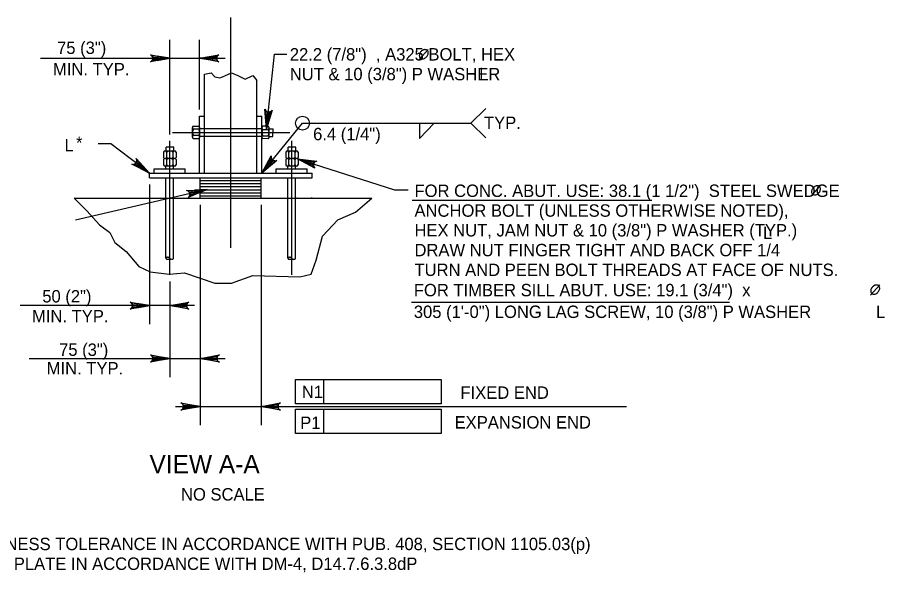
# Model space of a CAD drawing. Extents: x -13 to 81, y -176 to 0.
# Drawn here: x 13.47 to 21.86, y -148.39 to -143.01 of the extents above; entities that cross this region are included whole.
import ezdxf

# ---------------------------------------------------------------- set-up
doc = ezdxf.new("R2010")
doc.units = 0
for name, color, linetype in [('Level 3', 7, 'Continuous'), ('Level 4', 7, 'Continuous'), ('Level 52', 7, 'Continuous')]:
    doc.layers.add(name, color=color, linetype=linetype)

msp = doc.modelspace()

# ---------------------------------------------------------------- linework, layer by layer
at = {"layer": 'Level 3'}
for p, q in [((15.5355, -145.2405), (15.5355, -143.0105)), ((15.2822, -144.5168), (15.2822, -143.5601)), ((15.7888, -144.5168), (15.7888, -143.6213)), ((15.235, -143.9656), (15.2822, -143.9656)), ((15.235, -144.5168), (15.235, -143.9656)), ((15.7888, -143.9656), (15.836, -143.9656)), ((15.836, -144.5168), (15.836, -143.9656)), ((15.1642, -144.1685), (15.1645, -144.0775)), ((15.2265, -144.0938), (15.175, -144.0936)), ((15.1752, -144.0626), (15.2266, -144.0627)), ((15.2368, -144.1687), (15.2371, -144.0778)), ((15.2371, -144.0861), (15.836, -144.0861)), ((15.8358, -144.1703), (15.836, -144.0793)), ((15.8466, -144.0954), (15.898, -144.0955)), ((15.8981, -144.0645), (15.8467, -144.0644)), ((15.9085, -144.1705), (15.9087, -144.0795)), ((15.9087, -144.0887), (15.9448, -144.0888)), ((15.9447, -144.1625), (15.9448, -144.0888)), ((14.9705, -144.1231), (16.1081, -144.1231)), ((15.1747, -144.1825), (15.2262, -144.1827)), ((15.2263, -144.1538), (15.1748, -144.1536)), ((15.2369, -144.1608), (15.8358, -144.1608)), ((15.8464, -144.1554), (15.8979, -144.1555)), ((15.8978, -144.1844), (15.8464, -144.1843)), ((15.9085, -144.1624), (15.9447, -144.1625)), ((14.9107, -144.3038), (14.9108, -144.2676)), ((14.9846, -144.2678), (14.9108, -144.2676)), ((14.945, -145.5032), (14.945, -144.2057)), ((14.9845, -144.304), (14.9846, -144.2678)), ((16.1657, -144.2678), (16.0918, -144.2676)), ((16.0918, -144.3038), (16.0918, -144.2676)), ((16.1261, -145.5032), (16.1261, -144.2057)), ((16.1656, -144.304), (16.1657, -144.2678)), ((14.8865, -144.3144), (14.8864, -144.3658)), ((14.9926, -144.304), (14.9016, -144.3038)), ((14.9175, -144.3658), (14.9176, -144.3144)), ((14.9774, -144.366), (14.9776, -144.3146)), ((15.0065, -144.3146), (15.0064, -144.3661)), ((16.0677, -144.3144), (16.0675, -144.3658)), ((16.1737, -144.304), (16.0827, -144.3038)), ((16.0986, -144.3658), (16.0987, -144.3144)), ((16.1586, -144.366), (16.1587, -144.3146)), ((16.1876, -144.3146), (16.1875, -144.3661)), ((14.8864, -144.387), (14.8862, -144.4384)), ((14.9923, -144.4493), (14.9012, -144.4491)), ((14.9924, -144.3767), (14.9014, -144.3764)), ((14.908, -144.4774), (14.908, -144.4491)), ((14.9173, -144.4385), (14.9174, -144.3871)), ((14.9773, -144.4387), (14.9774, -144.3872)), ((14.9827, -144.4774), (14.9827, -144.4493)), ((15.0063, -144.3872), (15.0062, -144.4387)), ((16.0675, -144.387), (16.0674, -144.4384)), ((16.1733, -144.4493), (16.0823, -144.4491)), ((16.1735, -144.3767), (16.0825, -144.3764)), ((16.0891, -144.4774), (16.0891, -144.4491)), ((16.0984, -144.4385), (16.0985, -144.3871)), ((16.1584, -144.4387), (16.1585, -144.3872)), ((16.1638, -144.4774), (16.1638, -144.4493)), ((16.1874, -144.3872), (16.1873, -144.4387)), ((14.7481, -144.564), (14.7481, -144.5168)), ((14.7481, -144.5168), (16.3229, -144.5168)), ((14.7953, -144.5168), (14.7953, -144.4774)), ((14.7953, -144.4774), (15.0946, -144.4774)), ((15.0946, -144.5168), (15.0946, -144.4774)), ((15.9764, -144.4774), (16.2757, -144.4774)), ((15.9764, -144.5168), (15.9764, -144.4774)), ((16.2757, -144.5168), (16.2757, -144.4774)), ((16.3229, -144.564), (16.3229, -144.5168)), ((14.7481, -144.564), (16.3229, -144.564)), ((14.908, -144.7608), (14.908, -144.564)), ((14.9827, -144.7608), (14.9827, -144.564)), ((15.2402, -144.7608), (15.2402, -144.564)), ((15.2402, -144.5893), (15.5355, -144.5893)), ((15.2402, -144.6188), (15.5355, -144.6188)), ((15.5355, -144.5893), (15.8308, -144.5893)), ((15.5355, -144.6188), (15.8308, -144.6188)), ((15.8308, -144.7608), (15.8308, -144.564)), ((16.0891, -144.7608), (16.0891, -144.564)), ((16.1638, -144.7608), (16.1638, -144.564)), ((15.2402, -144.6483), (15.5355, -144.6483)), ((15.2402, -144.6779), (15.5355, -144.6779)), ((15.2402, -144.7074), (15.5355, -144.7074)), ((15.5355, -144.6483), (15.8308, -144.6483)), ((15.5355, -144.6779), (15.8308, -144.6779)), ((15.5355, -144.7074), (15.8308, -144.7074)), ((14.0217, -144.7608), (16.9022, -144.7608)), ((14.908, -145.3418), (14.908, -144.7608)), ((14.9827, -145.3421), (14.9827, -144.7608)), ((15.2402, -144.7369), (15.5355, -144.7369)), ((15.5355, -144.7369), (15.8308, -144.7369)), ((16.0891, -145.3418), (16.0891, -144.7608)), ((16.1638, -145.3421), (16.1638, -144.7608))]:
    msp.add_line(p, q, dxfattribs=at)
for points in [[(15.2822, -143.5601), (15.3455, -143.5478), (15.3823, -143.5846), (15.4313, -143.5968), (15.4558, -143.5846), (15.5417, -143.5478), (15.6029, -143.5723), (15.6765, -143.6091), (15.75, -143.5723), (15.7888, -143.6213)], [(14.7481, -144.5167), (14.5782, -144.4323), (14.5957, -144.4331), (14.6091, -144.4275), (14.6183, -144.4188), (14.6242, -144.4076), (14.6258, -144.3932), (14.6202, -144.3765), (14.7481, -144.5167), (14.6258, -144.3932), (14.6242, -144.4076), (14.7481, -144.5167), (14.6183, -144.4188), (14.6091, -144.4275), (14.7481, -144.5167), (14.5957, -144.4331)], [(15.2973, -144.6779), (15.1237, -144.7542), (15.1354, -144.7413), (15.1398, -144.7274), (15.1391, -144.7148), (15.1342, -144.7031), (15.1241, -144.6926), (15.1078, -144.6862), (15.2973, -144.6779), (15.1241, -144.6926), (15.1342, -144.7031), (15.2973, -144.6779), (15.1391, -144.7148), (15.1398, -144.7274), (15.2973, -144.6779), (15.1354, -144.7413)], [(14.0217, -144.7608), (14.1442, -144.8834), (14.2668, -145.0182), (14.3649, -145.0917), (14.4139, -145.1897), (14.5243, -145.2755), (14.6468, -145.4225), (14.7572, -145.4715), (14.941, -145.496), (15.0881, -145.4837), (15.3823, -145.5817), (15.5417, -145.5817), (15.75, -145.5083), (16.2036, -145.5205), (16.3139, -145.496), (16.3629, -145.3612), (16.4242, -145.1284), (16.5712, -144.9692), (16.7429, -144.8957), (16.9022, -144.7608)]]:
    msp.add_lwpolyline(points, dxfattribs=at)
for centre, radius, start, end in [((15.212, -144.1236), 0.0477, 140.8735, 218.7735), ((15.1811, -144.078), 0.0167, 111.11045, 181.65056), ((15.1811, -144.078), 0.0167, 181.65056, 248.53656), ((15.1893, -144.1235), 0.0477, 320.8735, 38.7735), ((15.2205, -144.0781), 0.0167, 291.11045, 357.99644), ((15.2205, -144.0781), 0.0167, 357.99644, 68.53656), ((15.8836, -144.1254), 0.0477, 140.93154, 218.83154), ((15.8527, -144.0798), 0.0167, 111.16848, 181.7086), ((15.8527, -144.0798), 0.0167, 181.7086, 248.59459), ((15.8609, -144.1253), 0.0477, 320.93154, 38.83154), ((15.892, -144.0799), 0.0167, 291.16848, 358.05448), ((15.892, -144.0799), 0.0167, 358.05448, 68.59459), ((15.1794, -144.1679), 0.0152, 107.27531, 252.37169), ((15.2217, -144.1681), 0.0152, 287.27531, 72.37169), ((15.851, -144.1698), 0.0152, 107.33335, 252.42973), ((15.8933, -144.1699), 0.0152, 287.33335, 72.42973), ((14.902, -144.3597), 0.0167, 201.16848, 271.7086), ((14.902, -144.3204), 0.0167, 88.05448, 158.59459), ((14.902, -144.3204), 0.0167, 21.16848, 88.05447), ((14.9475, -144.3287), 0.0477, 230.93154, 308.83154), ((14.9475, -144.3515), 0.0477, 50.93154, 128.83154), ((14.9919, -144.3614), 0.0152, 197.33335, 342.42973), ((14.992, -144.319), 0.0152, 17.33335, 162.42973), ((16.0831, -144.3597), 0.0167, 201.16848, 271.7086), ((16.0831, -144.3204), 0.0167, 88.05448, 158.59459), ((16.0831, -144.3597), 0.0167, 271.7086, 338.59459), ((16.0831, -144.3204), 0.0167, 21.16848, 88.05447), ((16.1286, -144.3287), 0.0477, 230.93154, 308.83154), ((16.1286, -144.3515), 0.0477, 50.93154, 128.83154), ((16.173, -144.3614), 0.0152, 197.33335, 342.42973), ((16.1731, -144.319), 0.0152, 17.33335, 162.42973), ((14.9018, -144.4323), 0.0167, 201.16848, 271.7086), ((14.9019, -144.393), 0.0167, 88.05448, 158.59459), ((14.9018, -144.4323), 0.0167, 271.7086, 338.59459), ((14.9019, -144.393), 0.0167, 21.16848, 88.05447), ((14.9474, -144.4014), 0.0477, 230.93154, 308.83154), ((14.9473, -144.4241), 0.0477, 50.93154, 128.83154), ((14.9918, -144.434), 0.0152, 197.33335, 342.42973), ((14.9919, -144.3917), 0.0152, 17.33335, 162.42973), ((16.0829, -144.4323), 0.0167, 201.16848, 271.7086), ((16.083, -144.393), 0.0167, 88.05448, 158.59459), ((16.0829, -144.4323), 0.0167, 271.7086, 338.59459), ((16.083, -144.393), 0.0167, 21.16848, 88.05447), ((16.1285, -144.4014), 0.0477, 230.93154, 308.83154), ((16.1284, -144.4241), 0.0477, 50.93154, 128.83154), ((16.1729, -144.434), 0.0152, 197.33335, 342.42973), ((16.173, -144.3917), 0.0152, 17.33335, 162.42973), ((14.9135, -145.3418), 0.00549, 142.06928, 180.00001), ((14.9135, -145.3418), 0.00549, 180.00001, 217.93074), ((14.9197, -145.3466), 0.0133, 117.99032, 142.06928), ((14.9197, -145.3369), 0.0133, 217.93074, 242.0097), ((14.9238, -145.3543), 0.0221, 102.4157, 117.99032), ((14.9238, -145.3292), 0.0221, 242.0097, 257.58432), ((14.9265, -145.3666), 0.0347, 90.00001, 102.4157), ((14.9265, -145.3169), 0.0347, 257.58432, 270.00001), ((14.9265, -145.3666), 0.0347, 77.58432, 90.00001), ((14.9265, -145.3169), 0.0347, 270.00001, 282.4157), ((14.9292, -145.3543), 0.0221, 62.0097, 77.58432), ((14.9292, -145.3292), 0.0221, 282.4157, 297.99032), ((14.9333, -145.3466), 0.0133, 37.93074, 62.0097), ((14.9333, -145.3369), 0.0133, 297.99032, 322.06928), ((14.9395, -145.3418), 0.00549, 0.00001, 37.93074), ((14.9395, -145.3418), 0.00549, 322.06928, 0.00001), ((14.9505, -145.3421), 0.00549, 179.99999, 217.93072), ((14.9566, -145.3373), 0.0133, 217.93072, 242.00968), ((14.9607, -145.3296), 0.0221, 242.00968, 257.5843), ((14.9634, -145.3173), 0.0347, 257.5843, 269.99999), ((14.9634, -145.3173), 0.0347, 269.99999, 282.41568), ((14.9662, -145.3296), 0.0221, 282.41568, 297.9903), ((14.9703, -145.3373), 0.0133, 297.9903, 322.06926), ((14.9764, -145.3421), 0.00549, 322.06926, 359.99999), ((14.9764, -145.3421), 0.00549, 359.99999, 1.75704), ((16.0946, -145.3418), 0.00549, 142.06928, 180.00001), ((16.0946, -145.3418), 0.00549, 180.00001, 217.93074), ((16.1008, -145.3466), 0.0133, 117.99032, 142.06928), ((16.1008, -145.3369), 0.0133, 217.93074, 242.0097), ((16.1049, -145.3543), 0.0221, 102.4157, 117.99032), ((16.1049, -145.3292), 0.0221, 242.0097, 257.58432), ((16.1076, -145.3666), 0.0347, 90.00001, 102.4157), ((16.1076, -145.3169), 0.0347, 257.58432, 270.00001), ((16.1076, -145.3666), 0.0347, 77.58432, 90.00001), ((16.1076, -145.3169), 0.0347, 270.00001, 282.4157), ((16.1103, -145.3543), 0.0221, 62.0097, 77.58432), ((16.1103, -145.3292), 0.0221, 282.4157, 297.99032), ((16.1144, -145.3466), 0.0133, 37.93074, 62.0097), ((16.1144, -145.3369), 0.0133, 297.99032, 322.06928), ((16.1206, -145.3418), 0.00549, 0.00001, 37.93074), ((16.1206, -145.3418), 0.00549, 322.06928, 0.00001), ((16.1316, -145.3421), 0.00549, 179.99999, 217.93072), ((16.1377, -145.3373), 0.0133, 217.93072, 242.00968), ((16.1418, -145.3296), 0.0221, 242.00968, 257.5843), ((16.1445, -145.3173), 0.0347, 257.5843, 269.99999), ((16.1445, -145.3173), 0.0347, 269.99999, 282.41568), ((16.1473, -145.3296), 0.0221, 282.41568, 297.9903), ((16.1514, -145.3373), 0.0133, 297.9903, 322.06926), ((16.1575, -145.3421), 0.00549, 322.06926, 359.99999), ((16.1575, -145.3421), 0.00549, 359.99999, 1.75704)]:
    msp.add_arc(centre, radius, start, end, dxfattribs=at)
at = {"layer": 'Level 4'}
for p, q in [((14.945, -144.1432), (14.945, -143.2267)), ((15.235, -143.9031), (15.235, -143.2267)), ((17.3581, -143.4196), (17.4477, -143.3215)), ((13.696, -143.4067), (15.4802, -143.4067)), ((15.8818, -144.0886), (15.9601, -143.3666)), ((15.9601, -143.3666), (16.0801, -143.3666)), ((17.8608, -144.0344), (18.0057, -143.8913)), ((15.836, -144.5168), (16.2301, -144.0344)), ((16.2301, -144.0344), (17.8608, -144.0344)), ((17.3622, -144.0344), (17.3622, -144.1812)), ((17.3622, -144.1812), (17.5036, -144.0344)), ((17.8608, -144.0344), (18.0057, -144.1775)), ((14.3738, -144.2345), (14.2538, -144.2345)), ((14.7481, -144.5167), (14.3738, -144.2345)), ((15.2973, -144.6779), (14.034, -144.9719)), ((14.7481, -144.6265), (14.7481, -145.9802)), ((21.1541, -144.737), (21.2437, -144.6389)), ((16.1746, -144.7608), (16.1795, -144.7559)), ((16.1795, -144.7559), (16.1844, -144.7608)), ((16.316, -144.7608), (16.3229, -144.7539)), ((17.292, -144.7788), (19.6116, -144.7788)), ((15.2402, -144.8233), (15.2402, -146.9558)), ((15.8308, -144.8233), (15.8308, -146.9558)), ((14.945, -145.5657), (14.945, -146.4907)), ((21.7267, -145.6973), (21.8163, -145.5992)), ((17.2857, -145.7659), (20.3634, -145.7659)), ((15.1837, -145.8002), (13.4983, -145.8002)), ((13.5851, -146.3107), (15.4802, -146.3107)), ((16.1616, -146.5152), (16.4354, -146.5152)), ((16.1616, -146.7514), (16.1616, -146.5152)), ((16.4354, -146.7514), (16.4354, -146.5152)), ((16.4354, -146.5152), (17.5737, -146.5152)), ((17.5737, -146.5152), (17.5737, -146.7514)), ((15.0015, -146.7758), (19.3649, -146.7758)), ((17.5737, -146.7514), (16.1616, -146.7514)), ((16.1616, -146.8026), (16.4354, -146.8026)), ((16.1616, -147.0387), (16.1616, -146.8026)), ((16.4354, -147.0387), (16.4354, -146.8026)), ((16.4354, -146.8026), (17.5737, -146.8026)), ((17.5737, -146.8026), (17.5737, -147.0387)), ((17.5737, -147.0387), (16.1616, -147.0387))]:
    msp.add_line(p, q, dxfattribs=at)
for points in [[(14.945, -143.4067), (14.7586, -143.4416), (14.7729, -143.4317), (14.7803, -143.4192), (14.7825, -143.4067), (14.7803, -143.3942), (14.7729, -143.3817), (14.7586, -143.3717), (14.945, -143.4067), (14.7729, -143.3817), (14.7803, -143.3942), (14.945, -143.4067), (14.7825, -143.4067), (14.7803, -143.4192), (14.945, -143.4067), (14.7729, -143.4317)], [(15.235, -143.4067), (15.4214, -143.3717), (15.4071, -143.3817), (15.3997, -143.3942), (15.3975, -143.4067), (15.3997, -143.4192), (15.4071, -143.4317), (15.4214, -143.4416), (15.235, -143.4067), (15.4071, -143.4317), (15.3997, -143.4192), (15.235, -143.4067), (15.3975, -143.4067), (15.3997, -143.3942), (15.235, -143.4067), (15.4071, -143.3817)], [(15.8818, -144.0886), (15.8671, -143.8995), (15.8754, -143.9148), (15.8871, -143.9236), (15.8993, -143.927), (15.9119, -143.9262), (15.9252, -143.9202), (15.9366, -143.907), (15.8818, -144.0886), (15.9252, -143.9202), (15.9119, -143.9262), (15.8818, -144.0886), (15.8993, -143.927), (15.8871, -143.9236), (15.8818, -144.0886), (15.8754, -143.9148)], [(15.836, -144.5168), (15.9269, -144.3502), (15.9255, -144.3677), (15.9305, -144.3813), (15.9388, -144.3909), (15.9498, -144.3972), (15.9642, -144.3993), (15.981, -144.3945), (15.836, -144.5168), (15.9642, -144.3993), (15.9498, -144.3972), (15.836, -144.5168), (15.9388, -144.3909), (15.9305, -144.3813), (15.836, -144.5168), (15.9255, -144.3677)], [(14.7481, -145.8002), (14.5617, -145.8351), (14.576, -145.8252), (14.5834, -145.8127), (14.5856, -145.8002), (14.5834, -145.7877), (14.576, -145.7752), (14.5617, -145.7653), (14.7481, -145.8002), (14.576, -145.7752), (14.5834, -145.7877), (14.7481, -145.8002), (14.5856, -145.8002), (14.5834, -145.8127), (14.7481, -145.8002), (14.576, -145.8252)], [(14.945, -145.8002), (15.1314, -145.7653), (15.1171, -145.7752), (15.1097, -145.7877), (15.1075, -145.8002), (15.1097, -145.8127), (15.1171, -145.8252), (15.1314, -145.8351), (14.945, -145.8002), (15.1171, -145.8252), (15.1097, -145.8127), (14.945, -145.8002), (15.1075, -145.8002), (15.1097, -145.7877), (14.945, -145.8002), (15.1171, -145.7752)], [(14.945, -146.3107), (14.7586, -146.3457), (14.7729, -146.3357), (14.7803, -146.3233), (14.7825, -146.3107), (14.7803, -146.2982), (14.7729, -146.2858), (14.7586, -146.2758), (14.945, -146.3107), (14.7729, -146.2858), (14.7803, -146.2982), (14.945, -146.3107), (14.7825, -146.3107), (14.7803, -146.3233), (14.945, -146.3107), (14.7729, -146.3357)], [(15.2402, -146.3107), (15.4267, -146.2758), (15.4123, -146.2858), (15.4049, -146.2982), (15.4027, -146.3107), (15.4049, -146.3233), (15.4123, -146.3357), (15.4267, -146.3457), (15.2402, -146.3107), (15.4123, -146.3357), (15.4049, -146.3233), (15.2402, -146.3107), (15.4027, -146.3107), (15.4049, -146.2982), (15.2402, -146.3107), (15.4123, -146.2858)], [(15.2402, -146.7758), (15.0538, -146.8107), (15.0682, -146.8008), (15.0756, -146.7883), (15.0777, -146.7758), (15.0756, -146.7633), (15.0682, -146.7508), (15.0538, -146.7409), (15.2402, -146.7758), (15.0682, -146.7508), (15.0756, -146.7633), (15.2402, -146.7758), (15.0777, -146.7758), (15.0756, -146.7883), (15.2402, -146.7758), (15.0682, -146.8008)], [(15.8308, -146.7758), (16.0172, -146.7409), (16.0028, -146.7508), (15.9954, -146.7633), (15.9932, -146.7758), (15.9954, -146.7883), (16.0028, -146.8008), (16.0172, -146.8107), (15.8308, -146.7758), (16.0028, -146.8008), (15.9954, -146.7883), (15.8308, -146.7758), (15.9932, -146.7758), (15.9954, -146.7633), (15.8308, -146.7758), (16.0028, -146.7508)]]:
    msp.add_lwpolyline(points, dxfattribs=at)
for points in [[(14.825, -143.3867), (14.825, -143.4267), (14.945, -143.4067)], [(15.355, -143.3867), (15.355, -143.4267), (15.235, -143.4067)], [(15.8771, -143.9466), (15.9168, -143.9508), (15.884, -144.068)], [(14.6643, -144.4286), (14.6402, -144.4605), (14.7481, -144.5168)], [(15.9274, -144.4365), (15.8964, -144.4112), (15.836, -144.5168)], [(15.1866, -144.6832), (15.1957, -144.7222), (15.308, -144.6755)], [(14.6281, -145.7802), (14.6281, -145.8202), (14.7481, -145.8002)], [(15.065, -145.7802), (15.065, -145.8202), (14.945, -145.8002)], [(14.825, -146.2908), (14.825, -146.3307), (14.945, -146.3107)], [(15.3602, -146.2908), (15.3602, -146.3307), (15.2402, -146.3107)], [(15.1202, -146.7558), (15.1202, -146.7958), (15.2402, -146.7758)], [(15.9507, -146.7558), (15.9507, -146.7958), (15.8308, -146.7758)]]:
    msp.add_lwpolyline(points, close=True, dxfattribs=at)
msp.add_circle((16.23, -144.0343), 0.0675, dxfattribs=at)
msp.add_arc((14.9505, -145.3418), 0.00549, 180.00001, 182.00778, dxfattribs=at)
for points in [[(17.4384, -143.3312), (17.4313, -143.3257), (17.4243, -143.3238), (17.4157, -143.3231), (17.4105, -143.3231), (17.402, -143.325), (17.394, -143.3287), (17.3886, -143.3317), (17.378, -143.3402), (17.3697, -143.351), (17.3647, -143.3611), (17.3618, -143.3703), (17.3608, -143.379), (17.3618, -143.3863), (17.3654, -143.3969), (17.3693, -143.4023), (17.3768, -143.4082), (17.3884, -143.411), (17.4017, -143.4106), (17.4184, -143.4029), (17.4306, -143.3925), (17.4398, -143.3798), (17.4458, -143.3665), (17.4477, -143.3518), (17.4452, -143.3423), (17.4388, -143.3312)], [(21.2344, -144.6486), (21.2273, -144.6432), (21.2203, -144.6412), (21.2117, -144.6405), (21.2065, -144.6405), (21.198, -144.6424), (21.19, -144.6461), (21.1846, -144.6492), (21.174, -144.6577), (21.1657, -144.6684), (21.1607, -144.6785), (21.1578, -144.6877), (21.1568, -144.6964), (21.1578, -144.7037), (21.1614, -144.7143), (21.1653, -144.7198), (21.1728, -144.7257), (21.1844, -144.7284), (21.1977, -144.728), (21.2144, -144.7203), (21.2266, -144.7099), (21.2357, -144.6972), (21.2417, -144.6839), (21.2437, -144.6693), (21.2412, -144.6598), (21.2348, -144.6486)], [(21.8071, -145.6089), (21.7999, -145.6035), (21.7929, -145.6016), (21.7843, -145.6008), (21.7791, -145.6008), (21.7706, -145.6027), (21.7626, -145.6064), (21.7572, -145.6095), (21.7466, -145.618), (21.7383, -145.6287), (21.7332, -145.6388), (21.7304, -145.6481), (21.7294, -145.6567), (21.7304, -145.6641), (21.7341, -145.6747), (21.7379, -145.6801), (21.7454, -145.686), (21.7571, -145.6887), (21.7703, -145.6883), (21.7871, -145.6807), (21.7993, -145.6702), (21.8084, -145.6575), (21.8144, -145.6442), (21.8164, -145.6296), (21.8137, -145.6201), (21.8074, -145.6089)]]:
    msp.add_spline(points, degree=3, dxfattribs=at)
at = {"layer": 'Level 52'}
for points in [[(16.1822, -144.3797), (17.121, -144.6791), (17.2528, -144.6791)], [(16.1822, -144.3798), (16.3704, -144.4032), (16.3537, -144.4083), (16.3428, -144.418), (16.337, -144.4292), (16.3352, -144.4418), (16.3385, -144.456), (16.3492, -144.4698), (16.1822, -144.3798), (16.3385, -144.456), (16.3352, -144.4418), (16.1822, -144.3798), (16.337, -144.4292), (16.3428, -144.418), (16.1822, -144.3798), (16.3537, -144.4083)]]:
    msp.add_lwpolyline(points, dxfattribs=at)

# ---------------------------------------------------------------- texts
at = {"layer": 'Level 4'}
for s, height, p in [('75 (3")', 0.12, (13.8551, -143.365)), ('22.2 (7/8")  , A325 BOLT, HEX', 0.12, (16.1075, -143.4282)), ('MIN. TYP.', 0.12, (13.8155, -143.5721)), ('NUT & 10 (3/8") P WASHER', 0.12, (16.1075, -143.6195)), ('L', 0.12, (17.9404, -143.6188)), ('TYP.', 0.12, (17.9867, -144.0902)), ('6.4 (1/4")', 0.12, (16.3328, -144.1995)), ('L', 0.12, (13.9267, -144.3067)), ('*', 0.12, (14.0387, -144.2843)), ('FOR CONC. ABUT. USE: 38.1 (1 1/2")  STEEL SWEDGE', 0.12, (17.314, -144.7485)), ('ANCHOR BOLT (UNLESS OTHERWISE NOTED), ', 0.12, (17.314, -144.9398)), ('HEX NUT, JAM NUT & 10 (3/8") P WASHER (TYP.)', 0.12, (17.314, -145.1309)), ('L', 0.12, (20.6867, -145.1557)), ('DRAW NUT FINGER TIGHT AND BACK OFF 1/4', 0.12, (17.314, -145.3222)), ('TURN AND PEEN BOLT THREADS AT FACE OF NUTS.', 0.12, (17.314, -145.5134)), ('FOR TIMBER SILL ABUT. USE: 19.1 (3/4")  x ', 0.12, (17.3077, -145.7096)), ('50 (2")', 0.12, (13.7118, -145.7692)), ('305 (1\'-0") LONG LAG SCREW, 10 (3/8") P WASHER', 0.12, (17.3077, -145.9196)), ('MIN. TYP.', 0.12, (13.6128, -145.9621)), ('L', 0.12, (21.7803, -145.9196)), ('75 (3")', 0.12, (13.8746, -146.2862)), ('MIN. TYP.', 0.12, (13.7546, -146.4661)), ('N1', 0.12, (16.224, -146.6941)), ('FIXED END', 0.12, (17.7587, -146.7018)), ('P1', 0.12, (16.2081, -146.9928)), ('EXPANSION END', 0.12, (17.7022, -146.9891)), ('VIEW A-A', 0.17717, (14.7497, -147.4219)), ('NO SCALE', 0.12, (15.0545, -147.6857)), ('(a) PROVIDE FLATNESS TOLERANCE IN ACCORDANCE WITH PUB. 408, SECTION 1105.03(p)', 0.12, (11.9561, -148.166)), ('(b) PROVIDE SOLE PLATE IN ACCORDANCE WITH DM-4, D14.7.6.3.8dP', 0.12, (11.9561, -148.3572))]:
    msp.add_text(s, height=height, dxfattribs=at).set_placement(p)

doc.saveas('drawing.dxf')
